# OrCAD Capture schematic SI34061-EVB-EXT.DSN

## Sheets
1 PAGE1: size B; title: Si34061-EVB-EXT-Interface -; rev: 1.7; note: SI34061-EVB-EXT
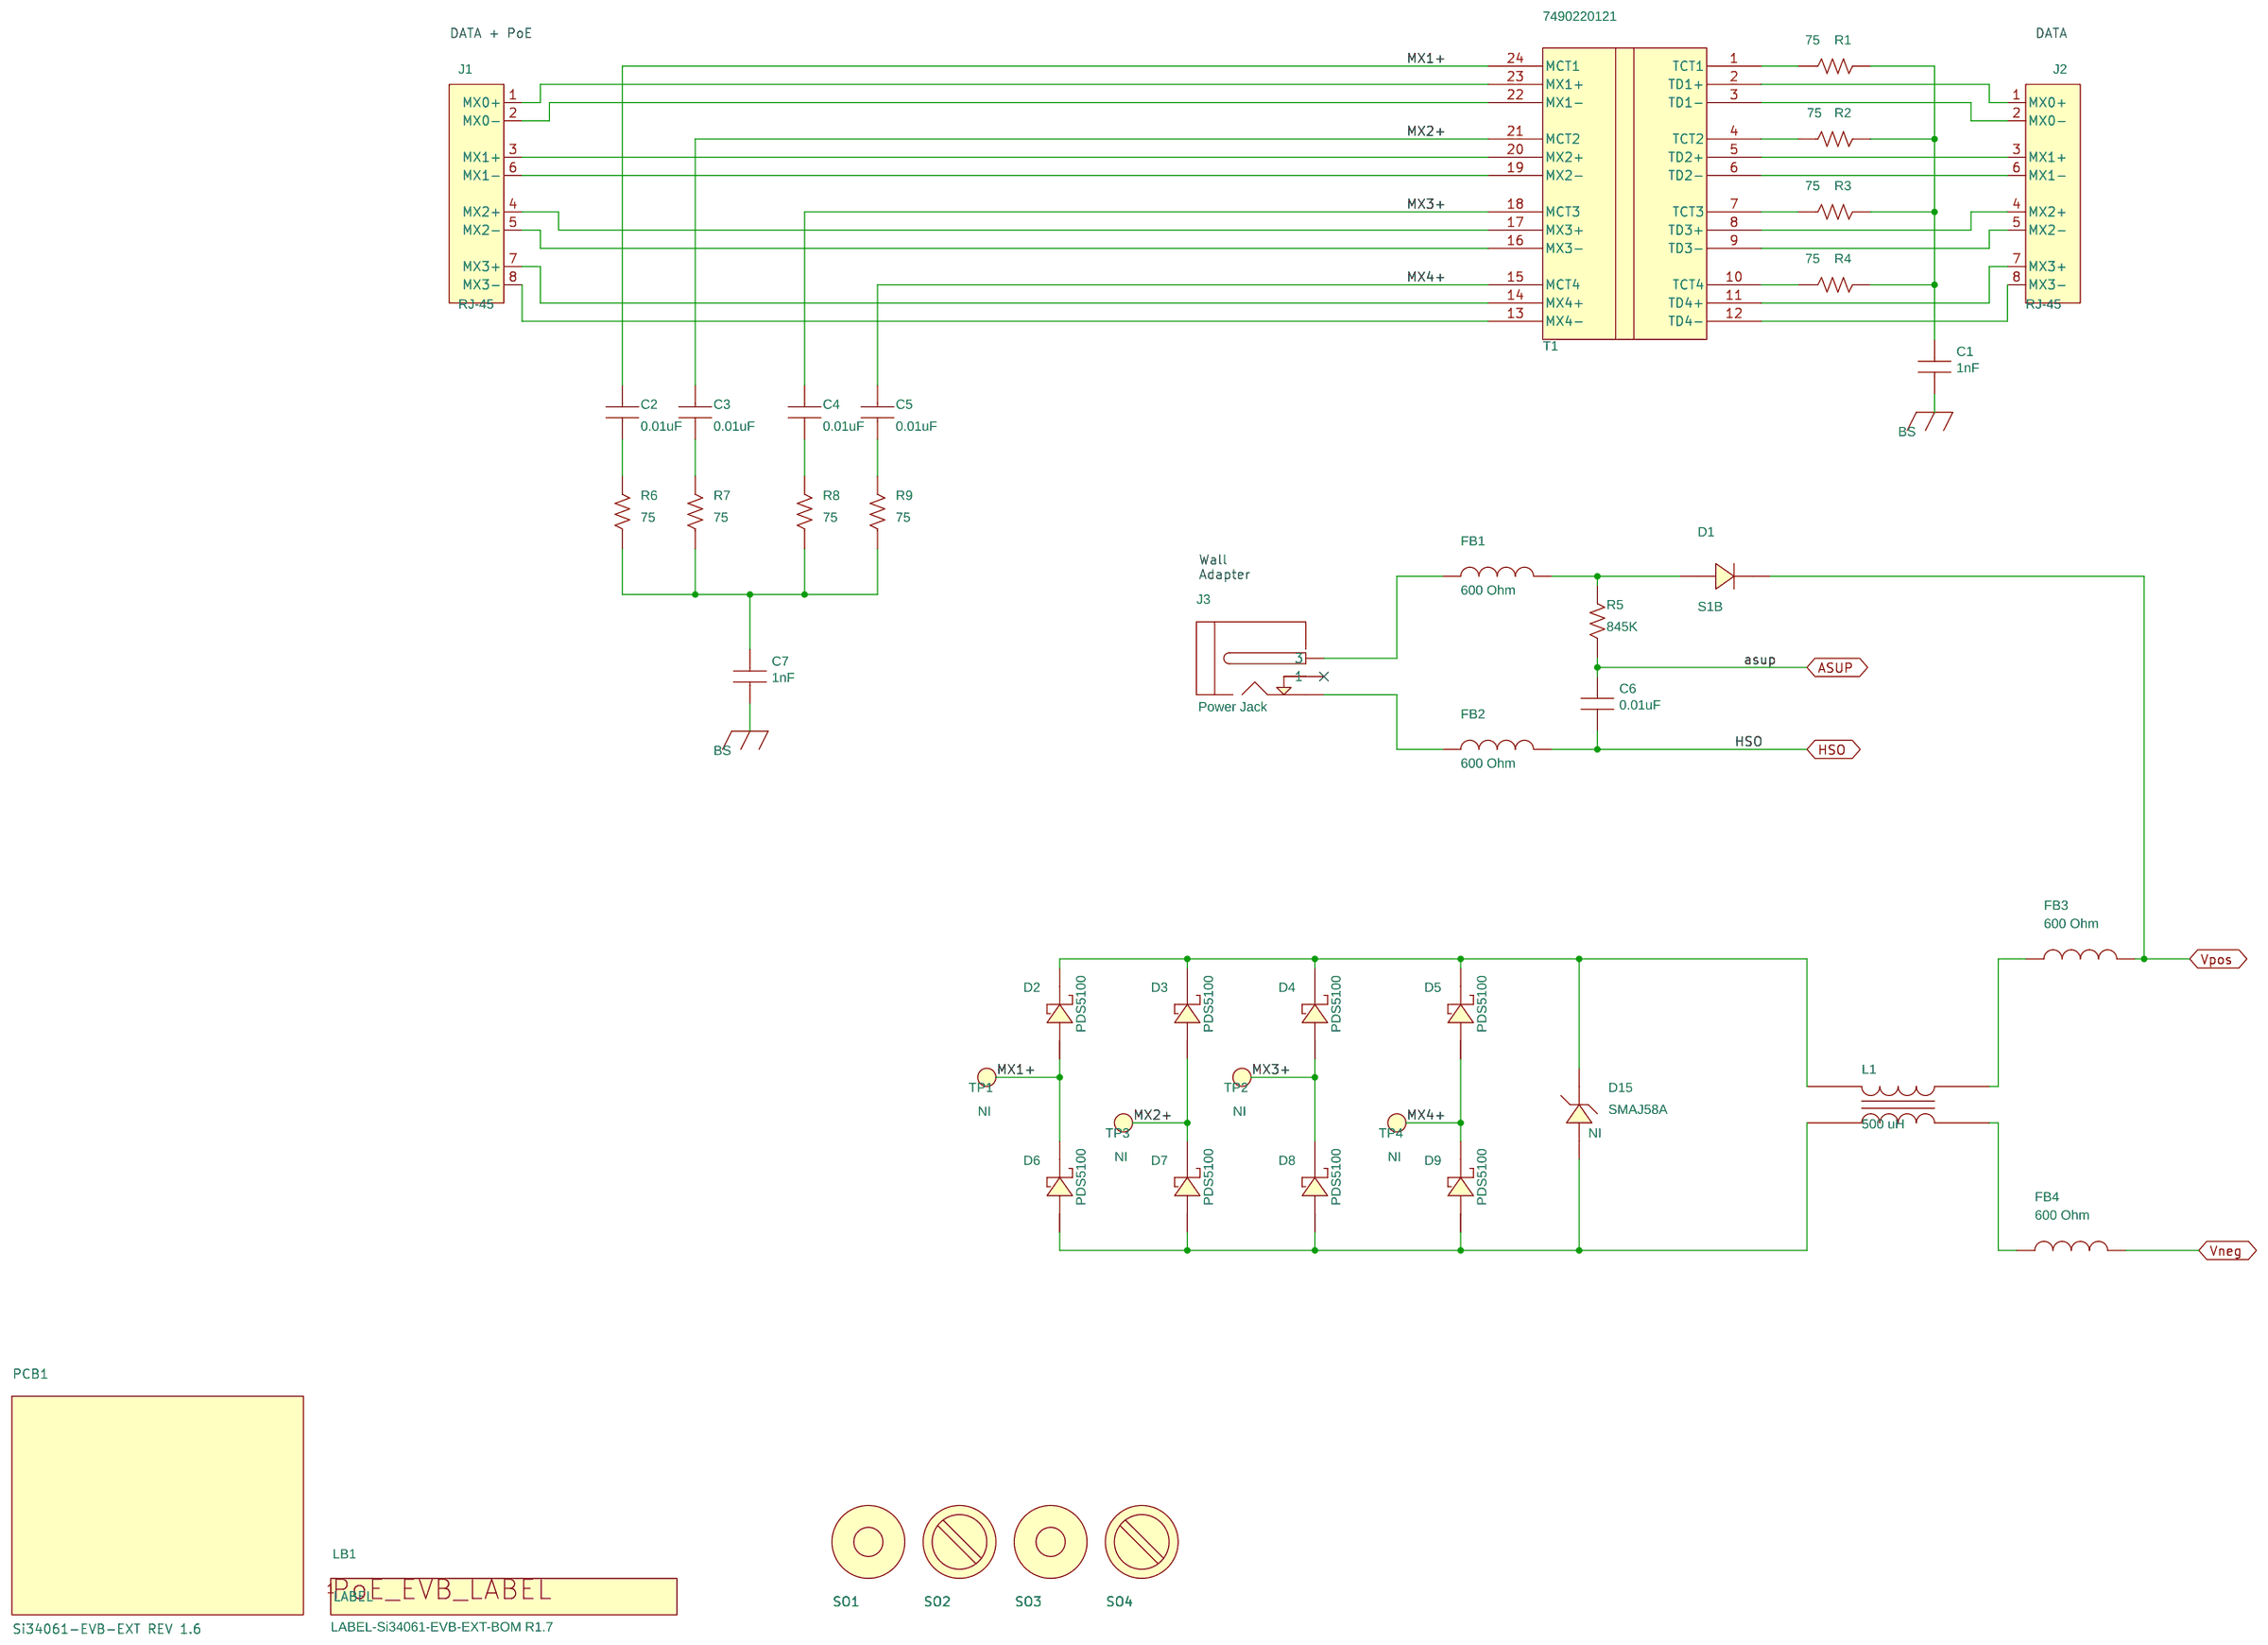
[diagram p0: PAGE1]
2 PAGE2: size B; title: Si34061-EVB-EXT-Converter -
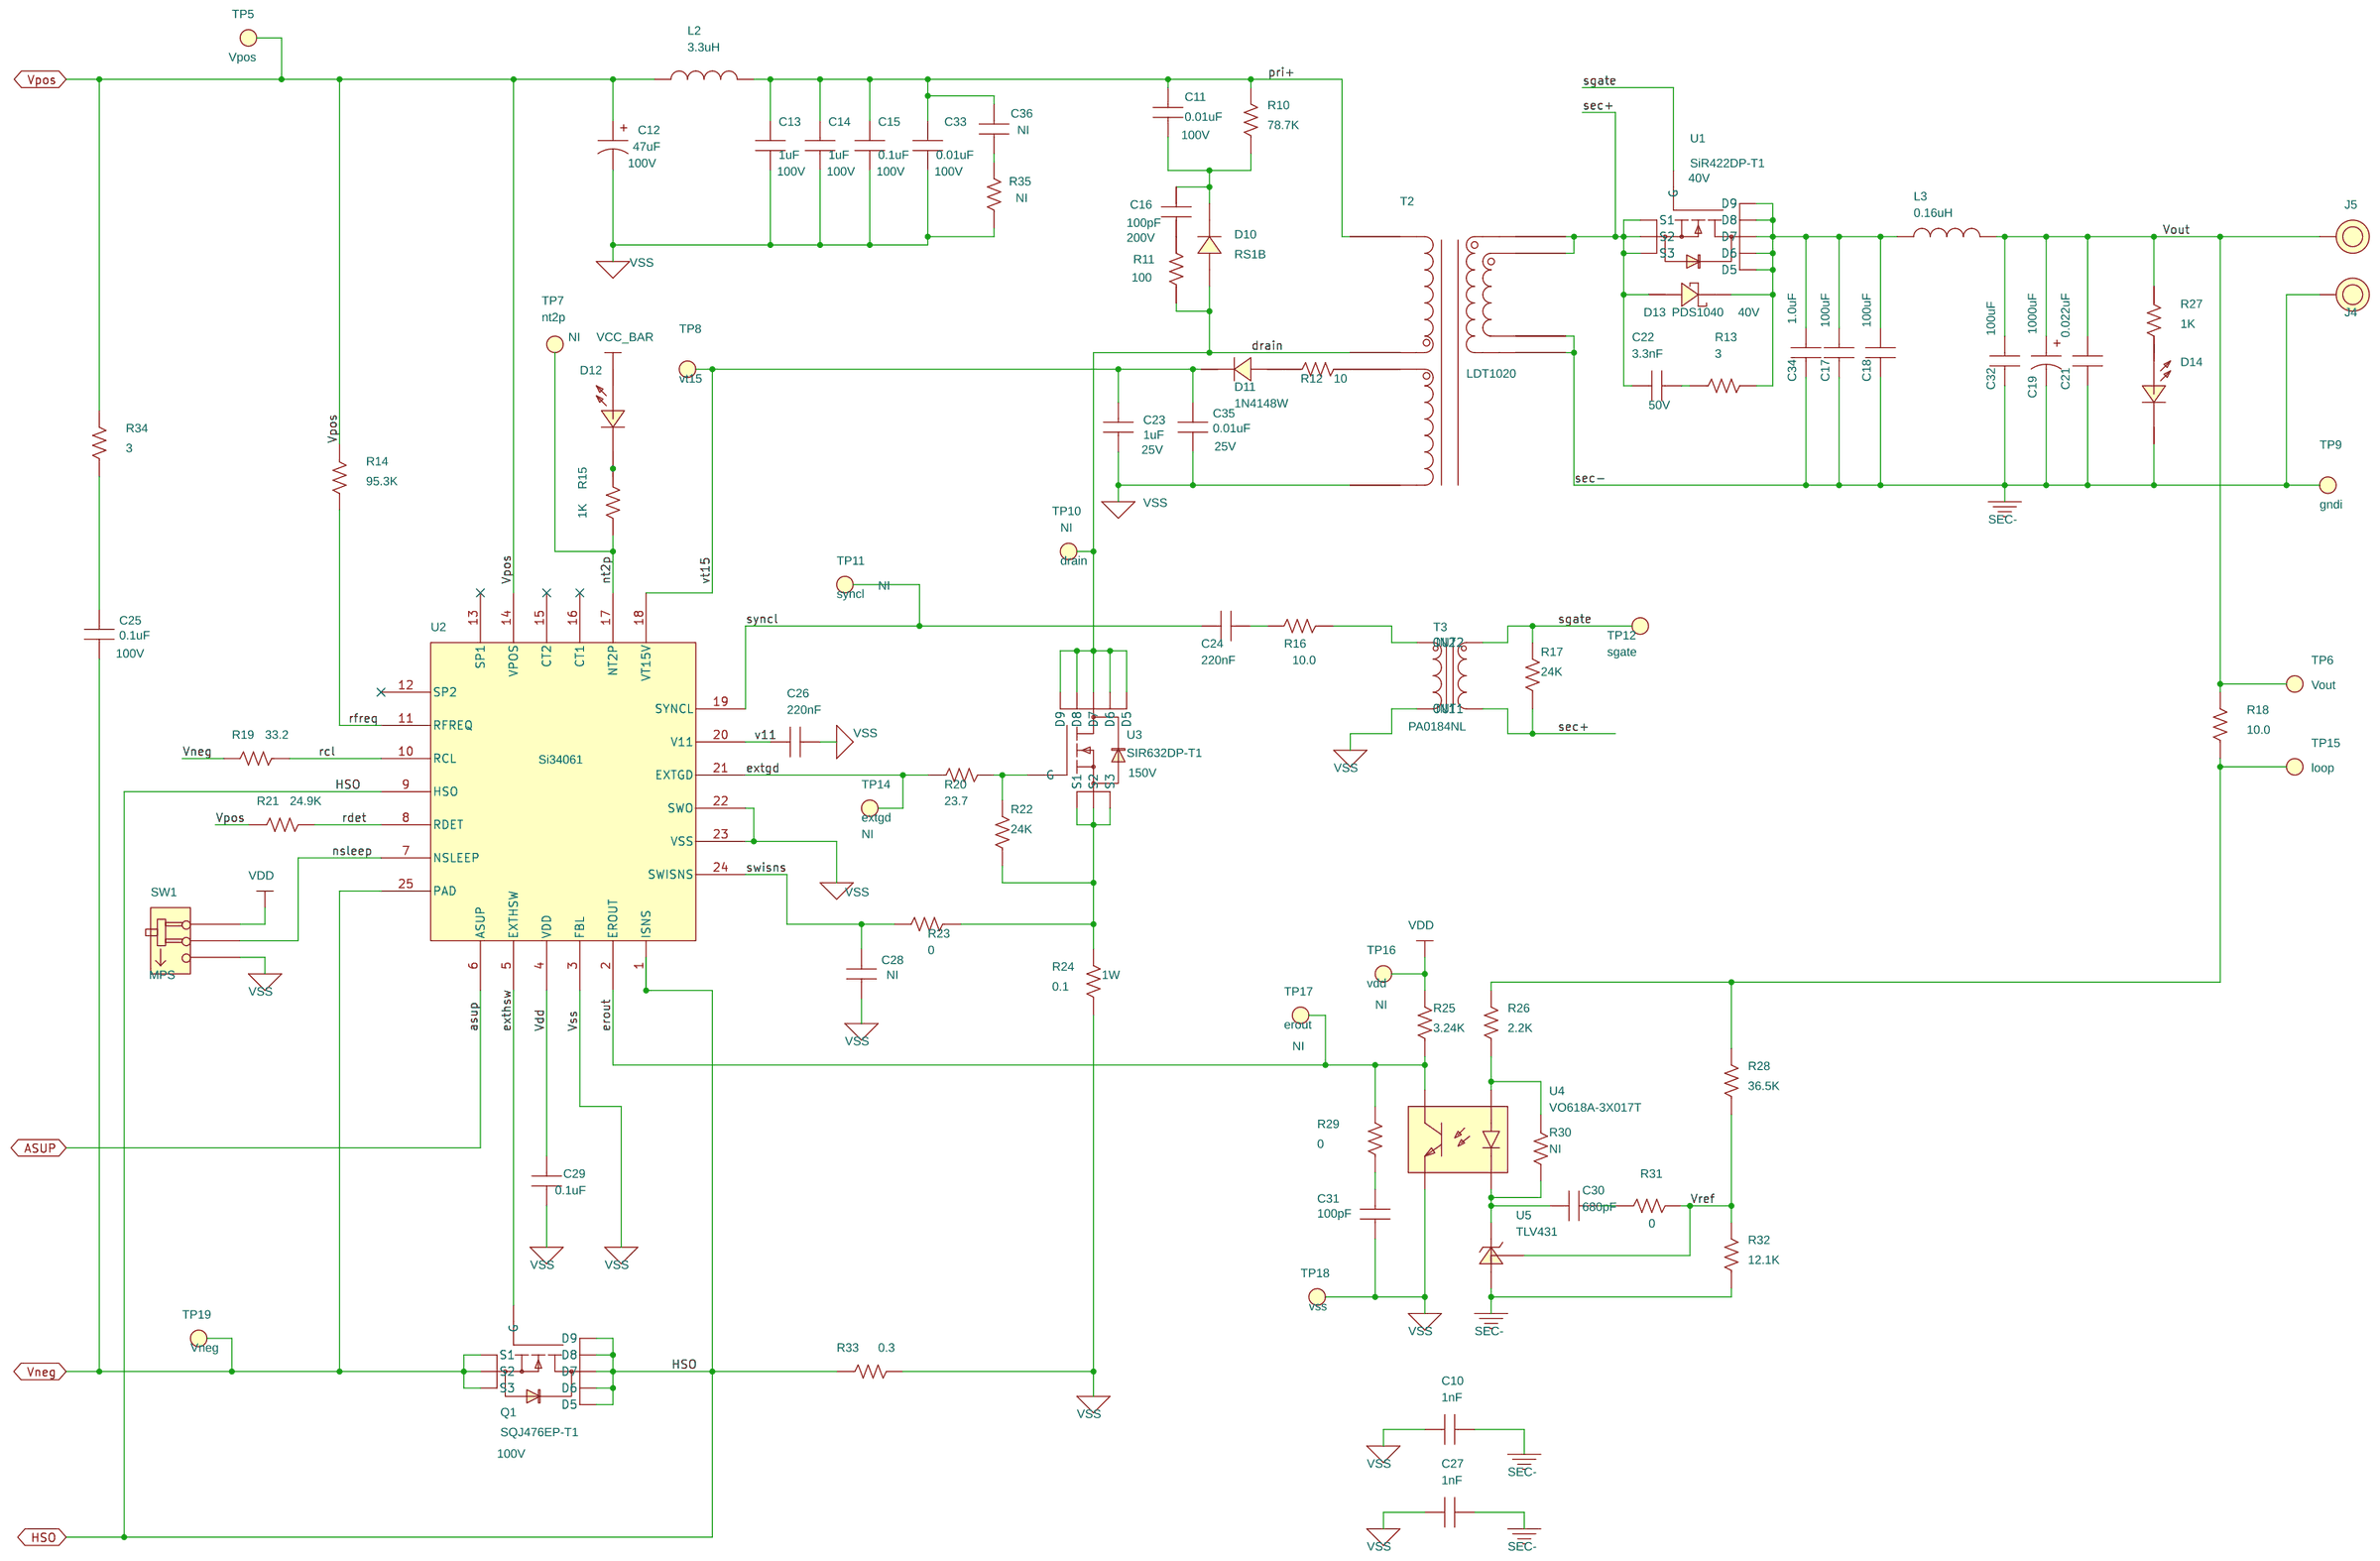
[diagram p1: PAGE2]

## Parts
sheet PAGE1
C1  1nF  [C1206]
C2  0.01uF  [C0603]
C3  0.01uF  [C0603]
C4  0.01uF  [C0603]
C5  0.01uF  [C0603]
C6  0.01uF  [C0805]
C7  1nF  [C1206]
D1  S1B  [DO-214AC]
D2  PDS5100  [POWERDI-5]
D3  PDS5100  [POWERDI-5]
D4  PDS5100  [POWERDI-5]
D5  PDS5100  [POWERDI-5]
D6  PDS5100  [POWERDI-5]
D7  PDS5100  [POWERDI-5]
D8  PDS5100  [POWERDI-5]
D9  PDS5100  [POWERDI-5]
D15  SMAJ58A  [DO-214AC]
FB1  600 Ohm  [L1206]
FB2  600 Ohm  [L1206]
FB3  600 Ohm  [L1206]
FB4  600 Ohm  [L1206]
J1  RJ-45  [RJ45-95001]
J2  RJ-45  [RJ45-95001]
J3  Power Jack  [CONN-3-PWR]
L1  500 uH  [IND-SRF0905]
LB1  LABEL-Si34061-EVB-EXT-BOM R1.7  [PTL-14-717]
MH1  4-40  [MH-125NP]
MH2  4-40  [MH-125NP]
MH3  4-40  [MH-125NP]
MH4  4-40  [MH-125NP]
PCB1  Si34061-EVB-EXT REV 1.6  [N/A]
R1  75  [R0603]
R2  75  [R0603]
R3  75  [R0603]
R4  75  [R0603]
R5  845K  [R0603]
R6  75  [R0603]
R7  75  [R0603]
R8  75  [R0603]
R9  75  [R0603]
SO1  STANDOFF
SO2  STANDOFF
SO3  STANDOFF
SO4  STANDOFF
T1  7490220121  [ETH-7490220121]
TP1  BLACK  [TESTPOINT]
TP2  BLACK  [TESTPOINT]
TP3  BLACK  [TESTPOINT]
TP4  BLACK  [TESTPOINT]
sheet PAGE2
C10  1nF  [C1206]
C11  0.01uF  [C0805]
C12  47uF  [C3.5X8MM-RAD]
C13  1uF  [C1210]
C14  1uF  [C1210]
C15  0.1uF  [C0603]
C16  100pF  [C0805]
C17  100uF  [C1210]
C18  100uF  [C1210]
C19  1000uF  [C3.5X8MM-RAD]
C21  0.022uF  [C0603]
C22  3.3nF  [C0805]
C23  1uF  [C0603]
C24  220nF  [C0603]
C25  0.1uF  [C0805]
C26  220nF  [C0603]
C27  1nF  [C1206]
C28  470pF  [C0402]
C29  0.1uF  [C0603]
C30  680pF  [C0805]
C31  100pF  [C0805]
C32  100uF  [C1210]
C33  0.01uF  [C0603]
C34  1.0uF  [C0402]
C35  0.01uF  [C0603]
C36  0.01uF  [C0805]
D10  RS1B  [DO-214AC]
D11  1N4148W  [SOD123]
D12  GREEN  [LED-0805-K]
D13  PDS1040  [POWERDI-5]
D14  GREEN  [LED-0805-K]
J4  BND_POST  [BANANA-JACK]
J5  BND_POST  [BANANA-JACK]
L2  3.3uH  [IND-8400]
L3  0.16uH  [IND-XAL50xx]
Q1  SQJ476EP-T1  [POWER56]
R10  78.7K  [R0805]
R11  100  [R0805]
R12  10  [R1206]
R13  3  [R0805]
R14  95.3K  [R0603]
R15  1K  [R0603]
R16  10.0  [R0603]
R17  24K  [R0603]
R18  10.0  [R0603]
R19  33.2  [R0603]
R20  23.7  [R0603]
R21  24.9K  [R0603]
R22  24K  [R0603]
R23  0  [R0603]
R24  0.1  [R1206]
R25  3.24K  [R0805]
R26  2.2K  [R0805]
R27  1K  [R0603]
R28  36.5K  [R0805]
R29  0  [R0805]
R30  1K  [R0603]
R31  0  [R0805]
R32  12.1K  [R0805]
R33  0.3  [R1206]
R34  3  [R0805]
R35  100  [R0805]
SW1  SW_SLIDE_2POS  [SW-SPDT-NK236H]
T2  LDT1020  [XFMR-LDT1020-50]
T3  1200uH  [XFMR-PA0184NL]
TP5  RED  [TESTPOINT]
TP6  RED  [TESTPOINT]
TP7  BLACK  [TESTPOINT]
TP8  BLACK  [TESTPOINT]
TP9  BLACK  [TESTPOINT]
TP10  BLACK  [TESTPOINT]
TP11  BLACK  [TESTPOINT]
TP12  BLACK  [TESTPOINT]
TP14  BLACK  [TESTPOINT]
TP15  BLACK  [TESTPOINT]
TP16  BLACK  [TESTPOINT]
TP17  BLACK  [TESTPOINT]
TP18  BLACK  [TESTPOINT]
TP19  BLACK  [TESTPOINT]
U1  SiR422DP-T1  [POWER56]
U2  Si34061  [QFN24M5X5P0.65E3.1]
U3  SIR632DP-T1  [POWER56]
U4  VO618A-3X017T  [SO4N10.16P2.54-AKEC]
U5  TLV431  [TLV431-DBZ]

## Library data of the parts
C1 C7 C10 C27 = CAP_NP: CAP, 1nF, 2000V, ±5%, X7R, 1206; Manufacturer: Kemet; ManufacturerPN: C1206C102JGRACTU; SiLabsPN: C1206C102JGRACTU; Tolerance: ±5%; Type: X7R; Voltage: 2000V; Datasheet: KEM_C1010_X7R_HV_SMD-1102742.pdf
C2-C5 C33 = CAP_NP: CAP, 0.01uF, 100V, ±10%, X7R, 0603; Manufacturer: Venkel; ManufacturerPN: C0603X7R101-103K; SiLabsPN: C0603X7R101-103K; Tolerance: ±10%; Type: X7R; Voltage: 100V; Datasheet: PID_C.pdf
C6 C11 = CAP_NP: CAP, 0.01uF, 100V, ±10%, X7R, 0805; Manufacturer: Venkel; ManufacturerPN: C0805X7R101-103K; SiLabsPN: C0805X7R101-103K; Tolerance: ±10%; Type: X7R; Voltage: 100V; Datasheet: PID_C.pdf
D1 = DIODE: DIO, SINGLE, 100V, 1.0A, SMA; Manufacturer: Fairchild; Rating: 1.0A; Type: Single; Voltage: 100V; Datasheet: S1A.pdf
D2-D9 = DIODE_SCHOTTKY_DUAL_ANODE_3PIN: DIO, SCHOTTKY, 100V, 5A, PowerDI-5; Manufacturer: Diodes Inc.; ManufacturerPN: PDS5100H-13; Rating: 5A; SiLabsPN: PDS5100H-13; Type: Schottky; Voltage: 100V; Datasheet: ds30471.pdf
D15 = DIODE_ZENER: DIO, TVS, UNIDIR, 58V, 400W; Installed component: NI; Manufacturer: Littelfuse; Rating: 400W; Type: GP; Voltage: 58V; Datasheet: smaj.pdf
FB1-FB4 = Ferrite_Bead: FERRITE BEAD, 600 Ohm @100MHZ, 1206; Manufacturer: MuRata; ManufacturerPN: BLM31PG601SN1; Rating: 1500mA; SiLabsPN: BLM31PG601SN1; Type: SMT; Datasheet: Murata BLM Ferrites.pdf
J1 = RJ45_1PORT: CONN, RJ-45, 1 Port, Tab Down, 0.050" Pitch, PTH; Manufacturer: MOLEX; ManufacturerPN: 095501-2881; SiLabsPN: 095501-2881; Silk: PoE+Data; Type: Receptacle; Datasheet: 0955012881_MODULAR_JACKS_PLUG-177556.pdf
J2 = RJ45_1PORT: CONN, RJ-45, 1 Port, Tab Down, 0.050" Pitch, PTH; Manufacturer: MOLEX; ManufacturerPN: 095501-2881; SiLabsPN: 095501-2881; Silk: Data; Type: Receptacle; Datasheet: 0955012881_MODULAR_JACKS_PLUG-177556.pdf
J3 = CONN_BARREL_3PIN_ALT: CONN, POWER JACK, RA, 2.1mm, PTH; Manufacturer: Adam Tech; ManufacturerPN: ADC-002-1; Rating: 1A; SiLabsPN: ADC-002-1; Type: BARREL; Datasheet: CatPg200-203.pdf
L1 = CHOKE_CM_4P_SRF0905: CM Choke, 500uH, 1A, 1K, SMT; Manufacturer: Bourns; ManufacturerPN: SRF0905-501Y; Rating: 0.15 ohm; SiLabsPN: SRF0905-501Y; Type: Ethernet; Voltage: 80VDC; Datasheet: SRF0905.pdf
LB1 = PoE_EVB_Label: LABEL, PDB, POLYIMIDE, WHITE, 1.00 in. X 0.187 in., FONT 2; Manufacturer: Skyworks; Type: POLYIMIDE, WHITE; Datasheet: Brady TLS2200 Label PTL-14-717.pdf
MH1-MH4 = SCREW-Small: HDW, SCREW, 4-40 x 1/4 in. Pan Head, Slotted, Nylon; Manufacturer: Richco Plastic Co; ManufacturerPN: NSS-4-4-01; SiLabsPN: NSS-4-4-01; Type: SCREW; Datasheet: RichcoPlasticCo_Screws.pdf
PCB1 = PCB: PCB, BARE BOARD, Si34061-EVB-EXT REV 1.6; Manufacturer: Skyworks; Type: BARE PCB
R1-R4 R6-R9 = RES: RES, 75 Ohm, 1/16W, ±0.5%, ThinFilm, 0603; Manufacturer: Susumu; ManufacturerPN: RR0816Q-750-D; Rating: 1/16W; SiLabsPN: RR0816Q-750-D; Tolerance: ±0.5%; Type: ThinFilm; Datasheet: products_12.pdf
R5 = RES: RES, 845K, 1/10W, ±1%, ThickFilm, 0603; FPLIST: R0603,R0603L; Manufacturer: Panasonic; ManufacturerPN: ERJ-3EKF8453V; Rating: 1/10W; SiLabsPN: ERJ-3EKF8453V; Tolerance: ±1%; Type: ThickFilm; Datasheet: AOA0000C304.pdf
SO1-SO4 = STANDOFF: HDW, STANDOFF, 4-40 X 1/2" , Nylon; Manufacturer: SPC Technology; ManufacturerPN: 2397; SiLabsPN: 2397; Datasheet: SPC_Technology_spacers.pdf
T1 = ETH-7490220121: Module, PoE+/PoE++ Magnetics, PULSE XFMR 1CT:1CT TX 1CT:1CT RX, SMD; Manufacturer: Wurth; Rating: 350uH; Type: Ethernet; Datasheet: 7490220121.pdf
TP1-TP4 = TEST_POINT: TESTPOINT, BLACK, PTH; Installed Components: NI; Manufacturer: Kobiconn; ManufacturerPN: 151-203-RC; SiLabsPN: 151-203; Type: Loop; Datasheet: KC-300780.pdf
C12 = CAP_POL_ALT: CAP, 47uF, 100V, ±20%, AL, RAD; Manufacturer: Panasonic; ManufacturerPN: ECA2AM470; SiLabsPN: ECA2AM470; Tolerance: ±20%; Type: Alum_Elec; Voltage: 100V; Datasheet: ABA0000CE12.pdf
C13 C14 = CAP_NP: CAP, 1uF, 100V, ±10%, X7R, 1210; Manufacturer: Venkel; ManufacturerPN: C1210X7R101-105K; SiLabsPN: C1210X7R101-105K; Tolerance: ±10%; Type: X7R; Voltage: 100V; Datasheet: PID_C.pdf
C15 = CAP_NP: CAP, 0.1uF, 100V, ±10%, X7R, 0603; Manufacturer: Venkel; ManufacturerPN: C0603X7R101-104K; SiLabsPN: C0603X7R101-104K; Tolerance: ±10%; Type: X7R; Voltage: 100V; Datasheet: PID_C.pdf
C16 = CAP_NP: CAP, 100pF, 200V, ±5%, NP0 HIGH Q, 0805; Manufacturer: Venkel; ManufacturerPN: C0805HQN201-101J; SiLabsPN: C0805HQN201-101J; Tolerance: ±5%; Type: NP0 HIGH Q; Voltage: 200V; Datasheet: PID_HQN.pdf
C17 C18 C32 = CAP_NP: CAP, 100uF, 6.3V, ±10%, X5R, 1210; Manufacturer: Venkel; ManufacturerPN: C1210X5R6R3-107K; SiLabsPN: C1210X5R6R3-107K; Tolerance: ±10%; Type: X5R; Voltage: 6.3V; Datasheet: PID_C.pdf
C19 = CAP_POL_ALT: CAP, 1000uF, 6.3V, ±20%, AL, 8X11.5MM; Manufacturer: Panasonic; ManufacturerPN: ECA0JM102; SiLabsPN: ECA0JM102; Tolerance: ±20%; Type: Alum_Elec; Voltage: 6.3V; Datasheet: ABA0000CE12.pdf
C21 = CAP_NP: CAP, 0.022uF, 50V, ±20%, X7R, 0603; Manufacturer: TDK Corporation; ManufacturerPN: C1608X7R1H223M; SiLabsPN: C0603X7R500-223M; Tolerance: ±20%; Type: X7R; Voltage: 50V; Datasheet: general_B11.pdf
C22 = CAP_NP: CAP, 3.3nF, 50V, ±5%, X7R, 0805; Manufacturer: Venkel; ManufacturerPN: C0805X7R500-332JNE; SiLabsPN: C0805X7R500-332J; Tolerance: ±5%; Type: X7R; Voltage: 50V; Datasheet: PID_C.pdf
C23 = CAP_NP: CAP, 1uF, 25V, ±10%, X5R, 0603; Manufacturer: Venkel; ManufacturerPN: C0603X5R250-105K; SiLabsPN: C0603X5R250-105K; Tolerance: ±10%; Type: X5R; Voltage: 25V; Datasheet: PID_C.pdf
C24 C26 = CAP_NP: CAP, 220nF, 16V, ±5%, X7R, 0603; Manufacturer: Kemet; ManufacturerPN: C0603C224J4RACTU; SiLabsPN: C0603X7R160-224J; Tolerance: ±5%; Type: X7R; Voltage: 16V; Datasheet: KEM_C1002_X7R_SMD.pdf
C25 = CAP_NP: CAP, 0.1uF, 100V, ±10%, X7R, 0805; Manufacturer: Venkel; ManufacturerPN: C0805X7R101-104K; SiLabsPN: C0805X7R101-104K; Tolerance: ±10%; Type: X7R; Voltage: 100V; Datasheet: PID_C.pdf
C28 = CAP_NP: CAP, 470pF, 25V, ±20%, X7R, 0402; Installed Component: NI; Manufacturer: Venkel; ManufacturerPN: C0402X7R250-471M; SiLabsPN: C0402X7R250-471M; Tolerance: ±20%; Type: X7R; Voltage: 25V; Datasheet: PID_C.pdf
C29 = CAP_NP: CAP, 0.1uF, 10V, ±10%, X7R, 0603; FPLIST: C0603,C0603L; Manufacturer: Venkel; ManufacturerPN: C0603X7R100-104K; SiLabsPN: C0603X7R100-104K; Tolerance: ±10%; Type: X7R; Voltage: 10V; Datasheet: PID_C.pdf
C30 = CAP_NP: CAP, 680pF, 25V, ±1%, C0G, 0805; Manufacturer: Venkel; ManufacturerPN: C0805C0G250-681FNP; SiLabsPN: C0805C0G250-681F; Tolerance: ±1%; Type: C0G; Voltage: 25V; Datasheet: PID_C.pdf
C31 = CAP_NP: CAP, 100pF, 50V, ±1%, C0G, 0805; Manufacturer: Venkel; ManufacturerPN: C0805C0G500-101F; SiLabsPN: C0805C0G500-101F; Tolerance: ±1%; Type: C0G; Voltage: 50V; Datasheet: PID_C.pdf
C34 = CAP_NP: CAP, 1.0uF, 6.3V, ±10%, X7R, 0402; Manufacturer: Murata; ManufacturerPN: GRM155R70J105KA12J; SiLabsPN: GRM155R70J105KA12J; Tolerance: ±10%; Type: X7R; Voltage: 6.3V; Datasheet: c02e.pdf
C35 = CAP_NP: CAP, 0.01uF, 25V, ±10%, X8R, 0603; FPLIST: C0603,C0603L; Manufacturer: KEMET; ManufacturerPN: C0603C103K3HACAUTO; Rating: -55°C to +150°C; SiLabsPN: C0603X8R250-103K; Tolerance: ±10%; Type: X8R; Voltage: 25V; Datasheet: KEM_C1007_X8R_ULTRA_150C_SMD.pdf
C36 = CAP_NP: CAP, 0.01uF, 100V, ±10%, X7R, 0805; Installed Component: NI; Manufacturer: Venkel; ManufacturerPN: C0805X7R101-103K; SiLabsPN: C0805X7R101-103K; Tolerance: ±10%; Type: X7R; Voltage: 100V; Datasheet: PID_C.pdf
D10 = DIODE: DIO, SINGLE, 100V, 1.0A, SMA; Manufacturer: Fairchild; Rating: 1.0A; Type: Single; Voltage: 100V; Datasheet: RS1A.pdf
D11 = DIODE: DIO, fAST, 100V, 2A, SOD123; Manufacturer: Diodes Inc; Rating: 2A; Type: Fast; Voltage: 100V; Datasheet: ds30086-60872.pdf
D12 = LED: LED, GREEN, 0805; Manufacturer: LITE_ON INC; ManufacturerPN: LTST-C170GKT; Rating: 30mA; SiLabsPN: LTST-C170GKT; Silk: Type II; Type: SMT; Voltage: 2.2V; Datasheet: LTST-C170GKT.pdf
D13 = DIODE_SCHOTTKY_DUAL_ANODE_3PIN: DIO, SCHOTTKY, 40V, 10A, POWERDI-5; Manufacturer: Diodes Inc.; ManufacturerPN: PDS1040-13; Rating: 10A; SiLabsPN: PDS1040-13; Type: Schottky; Voltage: 40V; Datasheet: ds30538-79818.pdf
D14 = LED: LED, GREEN, 0805; Manufacturer: LITE_ON INC; ManufacturerPN: LTST-C170GKT; Rating: 30mA; SiLabsPN: LTST-C170GKT; Type: SMT; Voltage: 2.2V; Datasheet: LTST-C170GKT.pdf
J4 = BINDING-POST: CONN, BANANA JACK, Threaded uninsulated; Manufacturer: ABBATRON HH SMITH; ManufacturerPN: 101; Rating: 15A; SiLabsPN: 101; Type: BANANA; Datasheet: SD-101.pdf
J5 = BINDING-POST: CONN, BANANA JACK, Threaded uninsulated; Manufacturer: ABBATRON HH SMITH; ManufacturerPN: 101; Rating: 15A; SiLabsPN: 101; Silk: +; Type: BANANA; Datasheet: SD-101.pdf
L2 = INDUCTOR: INDUCTOR, POWER, 3.3 uH, ±20%, 1.5A, Unshielded; Manufacturer: Murata; ManufacturerPN: 84332C; Rating: 1.5A; SiLabsPN: 84332C; Tolerance: ±20%; Type: Unshielded; Datasheet: kmp_8400.pdf
L3 = INDUCTOR: INDUCTOR, POWER, Shielded, 0.16uH, 31A, SMD; Manufacturer: Coilcraft; ManufacturerPN: XAL5030-161ME; Rating: 16A; SiLabsPN: XAL5030-161ME; Tolerance: ±20%; Type: Shielded; Datasheet: xal50xx-270657.pdf
Q1 = NFET_PWR_9PIN: TRANSISTOR, MOSFET, N-CHNL, 100V, 23A, POWERPAK-SO-8; Manufacturer: Vishay; ManufacturerPN: SQJ476EP-T1_GE3; Rating: 23A; SiLabsPN: SQJ476EP-T1_GE3; Type: N-CHNL; Voltage: 100V; Datasheet: sqj476ep.pdf
R10 = RES: RES, 78.7K, 1/8W, ±1%, ThickFilm, 0805; Manufacturer: Yageo; ManufacturerPN: RC0805FR-0778K7L; Rating: 1/8W; SiLabsPN: CR0805-8W-7872F; Tolerance: ±1%; Type: ThickFilm; Datasheet: PYu-RC_Group_51_RoHS_L_9-1314892.pdf
R11 = RES: RES, 100 Ohm, 1/10W, ±1%, ThickFilm, 0805; Manufacturer: Venkel; ManufacturerPN: CR0805-10W-1000F; Rating: 1/10W; SiLabsPN: CR0805-10W-1000F; Tolerance: ±1%; Type: ThickFilm; Datasheet: PID_CR.pdf
R12 = RES: RES, 10 Ohm, 1/4W, ±1%, ThickFilm, 1206; Manufacturer: Venkel; ManufacturerPN: CR1206-4W-10R0F; Rating: 1/4W; SiLabsPN: CR1206-4W-10R0F; Tolerance: ±1%; Type: ThickFilm; Datasheet: PID_CR.pdf
R13 R34 = RES: RES, 3 Ohm, 1/8W, ±1%, ThickFilm, 0805; Manufacturer: Venkel; ManufacturerPN: CR0805-8W-3R00FT; Rating: 1/8W; SiLabsPN: CR0805-8W-3R00F; Tolerance: ±1%; Type: ThickFilm; Datasheet: PID_CR.pdf
R14 = RES: RES, 95.3K, 1/16W, ±1%, ThickFilm, 0603; Manufacturer: Venkel; ManufacturerPN: CR0603-16W-9532F; Rating: 1/16W; SiLabsPN: CR0603-16W-9532F; Silk: 50kHz; Tolerance: ±1%; Type: ThickFilm; Datasheet: PID_CR.pdf
R15 R27 = RES: RES, 1K, 1/10W, ±1%, ThickFilm, 0603; Manufacturer: Venkel; ManufacturerPN: CR0603-10W-1001F; Rating: 1/10W; SiLabsPN: CR0603-10W-1001F; Tolerance: ±1%; Type: ThickFilm; Datasheet: PID_CR.pdf
R16 R18 = RES: RES, 10.0 Ohm, 1/16W, ±1%, ThickFilm, 0603; Manufacturer: Venkel; ManufacturerPN: CR0603-16W-10R0F; Rating: 1/16W; SiLabsPN: CR0603-16W-10R0F; Tolerance: ±1%; Type: ThickFilm; Datasheet: PID_CR.pdf
R17 R22 = RES: RES, 24K, 1/10W, ±1%, ThickFilm, 0603; Manufacturer: Panasonic; ManufacturerPN: ERJ-3EKF2402V; Rating: 1/10W; SiLabsPN: CR0603-10W-2402F; Tolerance: ±1%; Type: ThickFilm; Datasheet: AOA0000CE2.pdf
R19 = RES: RES, 33.2 Ohm, 1/16W, ±1%, ThickFilm, 0603; Manufacturer: Venkel; ManufacturerPN: CR0603-16W-33R2F; Rating: 1/16W; SiLabsPN: CR0603-16W-33R2F; Silk: Class 4; Tolerance: ±1%; Type: ThickFilm; Datasheet: PID_CR.pdf
R20 = RES: RES, 23.7 Ohm, 1/16W, ±1%, ThickFilm, 0603; Manufacturer: Venkel; ManufacturerPN: CR0603-16W-23R7F; Rating: 1/16W; SiLabsPN: CR0603-16W-23R7F; Tolerance: ±1%; Type: ThickFilm; Datasheet: PID_CR.pdf
R21 = RES: RES, 24.9K, 1/10W, ±1%, ThickFilm, 0603; Manufacturer: Venkel; ManufacturerPN: CR0603-10W-2492F; Rating: 1/10W; SiLabsPN: CR0603-10W-2492F; Tolerance: ±1%; Type: ThickFilm; Datasheet: PID_CR.pdf
R23 = RES: RES, 0 Ohm, 1A, ThickFilm, 0603; FPLIST: R0603,R0603L; Manufacturer: Panasonic; ManufacturerPN: ERJ-3GEY0R00V; Rating: 1A; SiLabsPN: ERJ-3GEY0R00V; Type: ThickFilm; Datasheet: AOA0000CE1.pdf
R24 = RES: RES, 0.1 Ohm, 1W, ±1%, ThickFilm, 1206; Manufacturer: Panasonic; ManufacturerPN: ERJ-8BWFR100V; Rating: 1W; SiLabsPN: CR1206-1W-R100F; Tolerance: ±1%; Type: ThickFilm; Datasheet: AOA0000CE3-72189.pdf
R25 = RES: RES, 3.24K, 1/8W, ±1%, ThickFilm, 0805; Manufacturer: Vishay; ManufacturerPN: CRCW08053K24FKEA; Rating: 1/8W; SiLabsPN: CR0805-8W-3241F; Tolerance: ±1%; Type: ThickFilm; Datasheet: dcrcwe3-109170.pdf
R26 = RES: RES, 2.2k, 1/10W, ±5%, ThickFilm, 0805; Manufacturer: Venkel; ManufacturerPN: CR0805-10W-222J; Rating: 1/10W; SiLabsPN: CR0805-10W-222J; Tolerance: ±5%; Type: ThickFilm; Datasheet: PID_CR.pdf
R28 = RES: RES, 36.5K, 1/10W, ±1%, ThickFilm, 0805; Manufacturer: Venkel; ManufacturerPN: CR0805-10W-3652F; Rating: 1/10W; SiLabsPN: CR0805-10W-3652F; Tolerance: ±1%; Type: ThickFilm; Datasheet: PID_CR.pdf
R29 R31 = RES: RES, 0 Ohm, 2A, ThickFilm, 0805; Manufacturer: Venkel; ManufacturerPN: CR0805-10W-000; Rating: 2A; SiLabsPN: CR0805-10W-000; Type: ThickFilm; Datasheet: PID_CR.pdf
R30 = RES: RES, 1K, 1/10W, ±1%, ThickFilm, 0603; Installed Component: NI; Manufacturer: Venkel; ManufacturerPN: CR0603-10W-1001F; Rating: 1/10W; SiLabsPN: CR0603-10W-1001F; Tolerance: ±1%; Type: ThickFilm; Datasheet: PID_CR.pdf
R32 = RES: RES, 12.1K, 1/10W, ±1%, ThickFilm, 0805; Manufacturer: Venkel; ManufacturerPN: CR0805-10W-1212F; Rating: 1/10W; SiLabsPN: CR0805-10W-1212F; Tolerance: ±1%; Type: ThickFilm; Datasheet: PID_CR.pdf
R33 = RES: RES, 0.3 Ohm, 1/2W, ±1%, ThickFilm, 1206; Manufacturer: Venkel; ManufacturerPN: LCR1206-R300F; Rating: 1/2W; SiLabsPN: CR1206-2W-R300F; Tolerance: ±1%; Type: ThickFilm; Datasheet: PID_CR.pdf
R35 = RES: RES, 100 Ohm, 1/10W, ±1%, ThickFilm, 0805; Installed Component: NI; Manufacturer: Venkel; ManufacturerPN: CR0805-10W-1000F; Rating: 1/10W; SiLabsPN: CR0805-10W-1000F; Tolerance: ±1%; Type: ThickFilm; Datasheet: PID_CR.pdf
SW1 = 100MIL_SLIDER_SWITCH: SWITCH, SPDT, SLIDE, ON-ON, 0.1 PITCH, 12V, PTH; Manufacturer: Apem Inc.; ManufacturerPN: NK236H; Rating: 0.5A @ 12VDC; SiLabsPN: NK236H; Silk: MPS; Type: SLIDE; Datasheet: switch-slide-NK-ENG.pdf
T2 = XFMR-LDT1020: TRANSFORMER, Flyback, 30W, 1:0.315:0.421, SMD; Manufacturer: LinkCom; Rating: 30W; Type: FLYBACK; Datasheet: LDT1020-50.pdf
T3 = XFMR-PA0184NL: Gate XFMR, 1:1, 1500Vrms, 1200uH, 27.2Vusec; Manufacturer: Pulse Engineering; ManufacturerPN: PA0184NL; Rating: none; SiLabsPN: PA0184NL; Tolerance: none; Voltage: 1500V; Datasheet: SPM2007_61-179963.pdf
TP5 = TEST_POINT: TESTPOINT, RED, 0.050 in. LOOP, PTH; Manufacturer: Keystone; ManufacturerPN: 5000; SiLabsPN: 5000; Silk: Vpos; Type: LOOP; Datasheet: Keystone_thm_datasheet.pdf
TP6 = TEST_POINT: TESTPOINT, RED, 0.050 in. LOOP, PTH; Manufacturer: Keystone; ManufacturerPN: 5000; SiLabsPN: 5000; Silk: Vout; Type: LOOP; Datasheet: Keystone_thm_datasheet.pdf
TP7 = TEST_POINT: TESTPOINT, BLACK, 0.050" LOOP, PTH; Installed Component: NI; Manufacturer: Keystone; ManufacturerPN: 5001; SiLabsPN: 5001; Silk: nt2p; Type: LOOP; Datasheet: Keystone_thm_datasheet.pdf
TP8 = TEST_POINT: TESTPOINT, BLACK, 0.050" LOOP, PTH; Manufacturer: Keystone; ManufacturerPN: 5001; SiLabsPN: 5001; Silk: vt15; Type: LOOP; Datasheet: Keystone_thm_datasheet.pdf
TP9 = TEST_POINT: TESTPOINT, BLACK, 0.050" LOOP, PTH; Manufacturer: Keystone; ManufacturerPN: 5001; SiLabsPN: 5001; Silk: gndi; Type: LOOP; Datasheet: Keystone_thm_datasheet.pdf
TP10 = TEST_POINT: TESTPOINT, BLACK, 0.050" LOOP, PTH; Installed Component: NI; Manufacturer: Keystone; ManufacturerPN: 5001; SiLabsPN: 5001; Silk: drain; Type: LOOP; Datasheet: Keystone_thm_datasheet.pdf
TP11 = TEST_POINT: TESTPOINT, BLACK, 0.050" LOOP, PTH; Installed Component: NI; Manufacturer: Keystone; ManufacturerPN: 5001; SiLabsPN: 5001; Silk: syncl; Type: LOOP; Datasheet: Keystone_thm_datasheet.pdf
TP12 = TEST_POINT: TESTPOINT, BLACK, 0.050" LOOP, PTH; Manufacturer: Keystone; ManufacturerPN: 5001; SiLabsPN: 5001; Silk: sgate; Type: LOOP; Datasheet: Keystone_thm_datasheet.pdf
TP14 = TEST_POINT: TESTPOINT, BLACK, 0.050" LOOP, PTH; Installed Component: NI; Manufacturer: Keystone; ManufacturerPN: 5001; SiLabsPN: 5001; Silk: extgd; Type: LOOP; Datasheet: Keystone_thm_datasheet.pdf
TP15 = TEST_POINT: TESTPOINT, BLACK, 0.050" LOOP, PTH; Manufacturer: Keystone; ManufacturerPN: 5001; SiLabsPN: 5001; Silk: loop; Type: LOOP; Datasheet: Keystone_thm_datasheet.pdf
TP16 = TEST_POINT: TESTPOINT, BLACK, 0.050" LOOP, PTH; Installed Components: NI; Manufacturer: Keystone; ManufacturerPN: 5001; SiLabsPN: 5001; Silk: vdd; Type: LOOP; Datasheet: Keystone_thm_datasheet.pdf
TP17 = TEST_POINT: TESTPOINT, BLACK, 0.050" LOOP, PTH; Installed Components: NI; Manufacturer: Keystone; ManufacturerPN: 5001; SiLabsPN: 5001; Silk: erout; Type: LOOP; Datasheet: Keystone_thm_datasheet.pdf
TP18 = TEST_POINT: TESTPOINT, BLACK, 0.050" LOOP, PTH; Manufacturer: Keystone; ManufacturerPN: 5001; SiLabsPN: 5001; Silk: vss; Type: LOOP; Datasheet: Keystone_thm_datasheet.pdf
TP19 = TEST_POINT: TESTPOINT, BLACK, 0.050" LOOP, PTH; Manufacturer: Keystone; ManufacturerPN: 5001; SiLabsPN: 5001; Silk: Vneg; Type: LOOP; Datasheet: Keystone_thm_datasheet.pdf
U1 = NFET_PWR_9PIN: TRANSISTOR, MOSFET, N-CHNL, 40V, 40A, POWERPAK-SO-8; Manufacturer: Vishay; ManufacturerPN: SiR422DP-T1-GE3; Rating: 40A; SiLabsPN: SiR422DP-T1-GE3; Type: N-CHNL; Voltage: 40V; Datasheet: sir422dp.pdf
U2 = Si34061: IC, IEEE 802.3-Compliant POE+ PD Interface, QFN24; Manufacturer: Skyworks; Datasheet: si3406x-datasheet.pdf
U3 = NFET_PWR_9PIN: TRANSISTOR, MOSFET, N-CHNL, 150V, 29A, POWERPAK-SO-8; Manufacturer: Vishay; ManufacturerPN: SIR632DP-T1-RE3; Rating: 29A; SiLabsPN: SIR632DP-T1-RE3; Type: N-CHNL; Voltage: 150V; Datasheet: sir632dp.pdf
U4 = OPTOCOUPLER: PHOTOCOUPLER, 5300Vrms Isolation, 4-PIN SMD; Manufacturer: Vishay; Datasheet: vo618a-244754.pdf
U5 = SHUNT_REG: IC, ADJ PREC SHUNT REG LV SOT-23 Voltage-Output 1.24 ~ 6V; Manufacturer: TI; ManufacturerPN: TLV431BCDBZR; SiLabsPN: TLV431BCDBZR; Type: SHUNT; Datasheet: tlv431a.pdf

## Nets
GNDI: C10.2 C17.2 C18.2 C19.2 C21.2 C27.2 C32.2 C34.2 D14.K(CATHODE) J4.1(BP) R32.1 T2.6 T2.7 TP9.1(Point) U5.A(Anode)
v11: C26.2 U2.20(V11)
Vdd: C29.2 D12.A(ANODE) R25.2 SW1.2 TP16.1(Point) U2.4(VDD)
Vss: C10.1 C12.2 C13.2 C14.2 C15.2 C23.2 C26.1 C27.1 C28.2 C29.1 C31.2 C33.2 C35.2 R24.1 R33.2 R35.1 SW1.3 T2.5 T3.8(IN1) TP18.1(Point) U2.3(FBL) U2.22(SWO) U2.23(VSS) U4.E(EMITTER)
ASUP: C6.1 R5.1 U2.6(ASUP)
BS: C1.2 C7.2
drain: D10.A(ANODE) R11.1 T2.3 TP10.1(Point) U3.5(D5) U3.6(D6) U3.7(D7) U3.8(D8) U3.9(D9)
erout: R25.1 R29.2 TP17.1(Point) U2.2(EROUT) U4.C(COLLECTOR)
extgd: R20.1 TP14.1(Point) U2.21(EXTGD)
exthsw: Q1.4(G) U2.5(EXTHSW)
HSO: C6.2 FB2.2 Q1.5(D5) Q1.6(D6) Q1.7(D7) Q1.8(D8) Q1.9(D9) R33.1 U2.1(ISNS) U2.9(HSO)
LABEL: LB1.1(LABEL)
MX1+: C2.2 D2.A1(ANODE) D2.A2(ANODE) D6.K(CATHODE) T1.24(MCT1) TP1.1(Point)
MX2+: C3.2 D3.A1(ANODE) D3.A2(ANODE) D7.K(CATHODE) T1.21(MCT2) TP3.1(Point)
MX3+: C4.2 D4.A1(ANODE) D4.A2(ANODE) D8.K(CATHODE) T1.18(MCT3) TP2.1(Point)
MX4+: C5.2 D5.A1(ANODE) D5.A2(ANODE) D9.K(CATHODE) T1.15(MCT4) TP4.1(Point)
nsleep: SW1.1 U2.7(NSLEEP)
nt2p: R15.2 TP7.1(Point) U2.17(NT2P)
pri+: C11.2 C13.1 C14.1 C15.1 C33.1 C36.2 L2.2 R10.2 T2.1
rcl: R19.1 U2.10(RCL)
rdet: R21.2 U2.8(RDET)
rfreq: R14.2 U2.11(RFREQ)
sec+: C22.1 D13.A1(ANODE) D13.A2(ANODE) R17.1 T2.9 T2.10 T3.5(OUT1) U1.1(S1) U1.2(S2) U1.3(S3)
sgate: R17.2 T3.4(OUT2) TP12.1(Point) U1.4(G)
swisns: C28.1 R23.2 U2.24(SWISNS)
syncl: C24.1 TP11.1(Point) U2.19(SYNCL)
Vneg: C25.2 FB4.2 Q1.1(S1) Q1.2(S2) Q1.3(S3) R19.2 TP19.1(Point) U2.25(PAD)
Vout: C19.1 C21.1 C32.1 J5.1(BP) L3.2 R18.2 R27.1 TP6.1(Point)
Vpos: C12.1 D1.K(CATHODE) FB3.2 L2.1 R14.1 R21.1 R34.2 TP5.1(Point) U2.14(VPOS)
Vref: R28.1 R31.2 R32.2 U5.REF(VREF)
vt15: C23.1 C35.1 D11.K(CATHODE) TP8.1(Point) U2.18(VT15V)
N176606: D6.A1(ANODE) D6.A2(ANODE) D7.A1(ANODE) D7.A2(ANODE) D8.A1(ANODE) D8.A2(ANODE) D9.A1(ANODE) D9.A2(ANODE) D15.A(ANODE) L1.2
N327229: D2.K(CATHODE) D3.K(CATHODE) D4.K(CATHODE) D5.K(CATHODE) D15.K(CATHODE) L1.1
N1572142: C11.1 C16.1 D10.K(CATHODE) R10.1
N1572186: C17.1 C18.1 C34.1 D13.K(CATHODE) L3.1 R13.2 U1.5(D5) U1.6(D6) U1.7(D7) U1.8(D8) U1.9(D9)
N1572190: R18.1 R26.2 R28.2 TP15.1(Point)
N1572220: C22.2 R13.1
N1572222: R26.1 R30.1 U4.A(ANODE)
N1572224: C30.2 R31.1
N1572278: R22.1 R23.1 R24.2 U3.1(S1) U3.2(S2) U3.3(S3)
N1572494: C31.1 R29.1
N1572496: C30.1 R30.2 U4.K(CATHODE) U5.K(Cathode)
N1572506: R16.1 T3.1(IN2)
N1572530: C24.2 R16.2
N1572718: D12.K(CATHODE) R15.1
N1578169: J2.6(MX1-) T1.6(TD2-)
N1578177: J2.5(MX2-) T1.9(TD3-)
N1578189: J2.8(MX3-) T1.12(TD4-)
N1578197: J2.7(MX3+) T1.11(TD4+)
N1578209: J2.3(MX1+) T1.5(TD2+)
N1578233: J2.2(MX0-) T1.3(TD1-)
N1578492: J2.1(MX0+) T1.2(TD1+)
N1578985: J1.6(MX1-) T1.19(MX2-)
N1579021: J1.5(MX2-) T1.16(MX3-)
N1579033: J1.8(MX3-) T1.13(MX4-)
N1579041: J1.7(MX3+) T1.14(MX4+)
N1579053: J1.3(MX1+) T1.20(MX2+)
N1579069: J1.2(MX0-) T1.22(MX1-)
N1579081: J1.1(MX0+) T1.23(MX1+)
N1579428: C1.1 R1.2 R2.2 R3.2 R4.2
N1579529: C2.1 R6.2
N1579577: C3.1 R7.2
N1579641: C4.1 R8.2
N1579705: C5.1 R9.2
N1579733: C7.1 R6.1 R7.1 R8.1 R9.1
N1583012: FB3.1 L1.4
N1583016: FB4.1 L1.3
N1585202: FB1.1 J3.1(3)
N1585210: FB2.1 J3.2
N1585234: D1.A(ANODE) FB1.2 R5.2
N1585890: J1.4(MX2+) T1.17(MX3+)
N1586017: R1.1 T1.1(TCT1)
N1586046: R2.1 T1.4(TCT2)
N1586058: R3.1 T1.7(TCT3)
N1586070: R4.1 T1.10(TCT4)
N1586305: J2.4(MX2+) T1.8(TD3+)
N1589566: R20.2 R22.2 U3.4(G)
N1660973: D14.A(ANODE) R27.2
N1667249: C25.1 R34.1
N1682558: C36.1 R35.2
N1722573: D11.A(ANODE) R12.1
N1722574: C16.2 R11.2
N1729737: R12.2 T2.4

Not connected (* = marked no-connect by the designer): J3 3(1)*; U2 12(SP2)* 13(SP1)* 15(CT2)* 16(CT1)*

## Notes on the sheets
sheet 1
- DATA + PoE
- DATA
- Wall
  Adapter
